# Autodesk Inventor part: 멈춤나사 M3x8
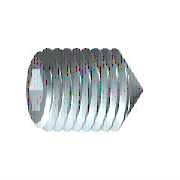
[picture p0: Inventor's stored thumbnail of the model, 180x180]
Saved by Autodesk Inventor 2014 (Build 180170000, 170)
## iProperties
IsCustomPart: 1
Created: 2012-02
Part Number: 멈춤나사 M3x8
Material: 강철, 연강
Description: 6각 소켓 머리 없는 멈춤 나사
Document SubType Name: Modeling
Standard: KS B 1028
Designer: test
Standards Organization: KS
Language: ko-KR
Size Designation: 원추점 M3x8
Categories: <MemberInstance><Categories><Category DisplayName="조임쇠" InternalName="e4da775c-781d-43d5-af7c-5136215cf5a6" Mnemonic="FSTN"><Category DisplayName="볼트" InternalN
Density: 1 g/cm^3
Appearance: Steel
Author: test
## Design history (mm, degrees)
sketch "스케치1"
  geometry: L1 (0, 0)-(5.5, 0); L2 (8, 0.866)-(8, 1.5); L3 (8, 1.5)-(0, 1.5); L4 (8, 0.866)-(6, 0.866); L5 (6, 0.866)-(5.5, 0); L6 (0, -0.3)-(0, 1.8) reference; L7 (0, 1.5)-(0, 0)
  constraints: 13 end point, 3 parallel, 1 collinear, 1 perpendicular, 1 point on line
  dimensions: "d0" = 2 distance of L2.start L4.end (= INTI); "d1" = 60 deg angle of L5 L1; "d2" = 3 diameter of L3 L1 (= NND); "d3" = 1.73205 diameter of L4 L1 (= 1.1547 x SW); "d5" = 8 distance from line of L2 L3.end (= NLG)
revolve "본체" sketch "스케치1" stored, may be unused: angle "d6" = 90 deg
sketch "스케치2"
  geometry: L1 (-0.433, 0.75)-(0.433, 0.75); L2 (0.433, 0.75)-(0.866, 0); L3 (0.866, 0)-(0.433, -0.75); L4 (0.433, -0.75)-(-0.433, -0.75); L5 (-0.433, -0.75)-(-0.866, 0); L6 (-0.866, 0)-(-0.433, 0.75); 3 further points
  constraints: 12 end point, 1 coincident, 1 horizontal, 13 other
extrude "슬롯" join sketch "스케치2" taper "d7" = 0 deg; stored distance "d21" = 10
workaxis "Work Axis1"
workplane "Work Plane1"
sketch "스케치4"
  geometry: L1 (0, 0.15)-(-1.35, 1.5) reference; L2 (0, -0.15)-(-1.35, -1.5) reference; L3 (-1.35, -1.5)-(0.15, 0); L4 (-1.35, 1.5)-(0.15, 0); 2 further points
  constraints: 4 end point, 1 coincident, 1 collinear, 1 horizontal alignment
body "Solid1"
feature "스레드" dims "d12" = 8 (= NLG), "d13" = 0
chamfer "모따기1" distance "d8" = 1.35 (computed from NND, SPD, FAWI); stored, may be unused: angle "d9" = 45 deg (= FAWI), second distance "d34" = 1.35 (computed from NND, SPD, FAWI)
chamfer "모따기2" distance "d10" = 0.30673 (= -0.5 x GD1 + 0.5 x NND); stored, may be unused: angle "d11" = 45 deg (= FAWI), second distance "d35" = 0.30673 (= -0.5 x GD1 + 0.5 x NND)
other parameters: "NND" = 3 [user parameter; used in 5 equation terms], "NLG" = 8 [user parameter; used in 2 equation terms], "INTI" = 2 [user parameter; used in 1 equation term], "FAWI" = 45 deg [user parameter; used in 4 equation terms], "SW" = 1.5 [user parameter; used in 2 equation terms], "GD1" = 2.38655 (= THREADDIA - 1.2269 x PTC) [user parameter; used in 2 equation terms], "d4" = 0, "FAWI1" = 45 deg [user parameter], "SPD" = 0.3 [user parameter; used in 2 equation terms], "d36" = 0, "d37" = 0, "GUL" = 0.30673 (= 0.61345 x PTC) [user parameter], "TOA" = 30 deg [user parameter], "THREADDIA" = 3 [user parameter; used in 1 equation term], "PTC" = 0.5 [user parameter; used in 4 equation terms], "GAL" = 0.30673 (= 0.61345 x PTC) [user parameter], "E0" = 1.7325 (= 1.155 x SW) [user parameter]
